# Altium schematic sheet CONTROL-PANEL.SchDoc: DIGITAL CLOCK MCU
size A4; Author: Én; Organization: PIF Club; Address1: Room 304, B1 Block; Address2: HCMUT; Address3: 268 Ly Thuong Kiet St.; Address4: Ward 14, District 10, HCMC; Revision: v1.0; SheetNumber: 2; SheetTotal: 2; ProjectTitle: DIGITAL CLOCK MCU
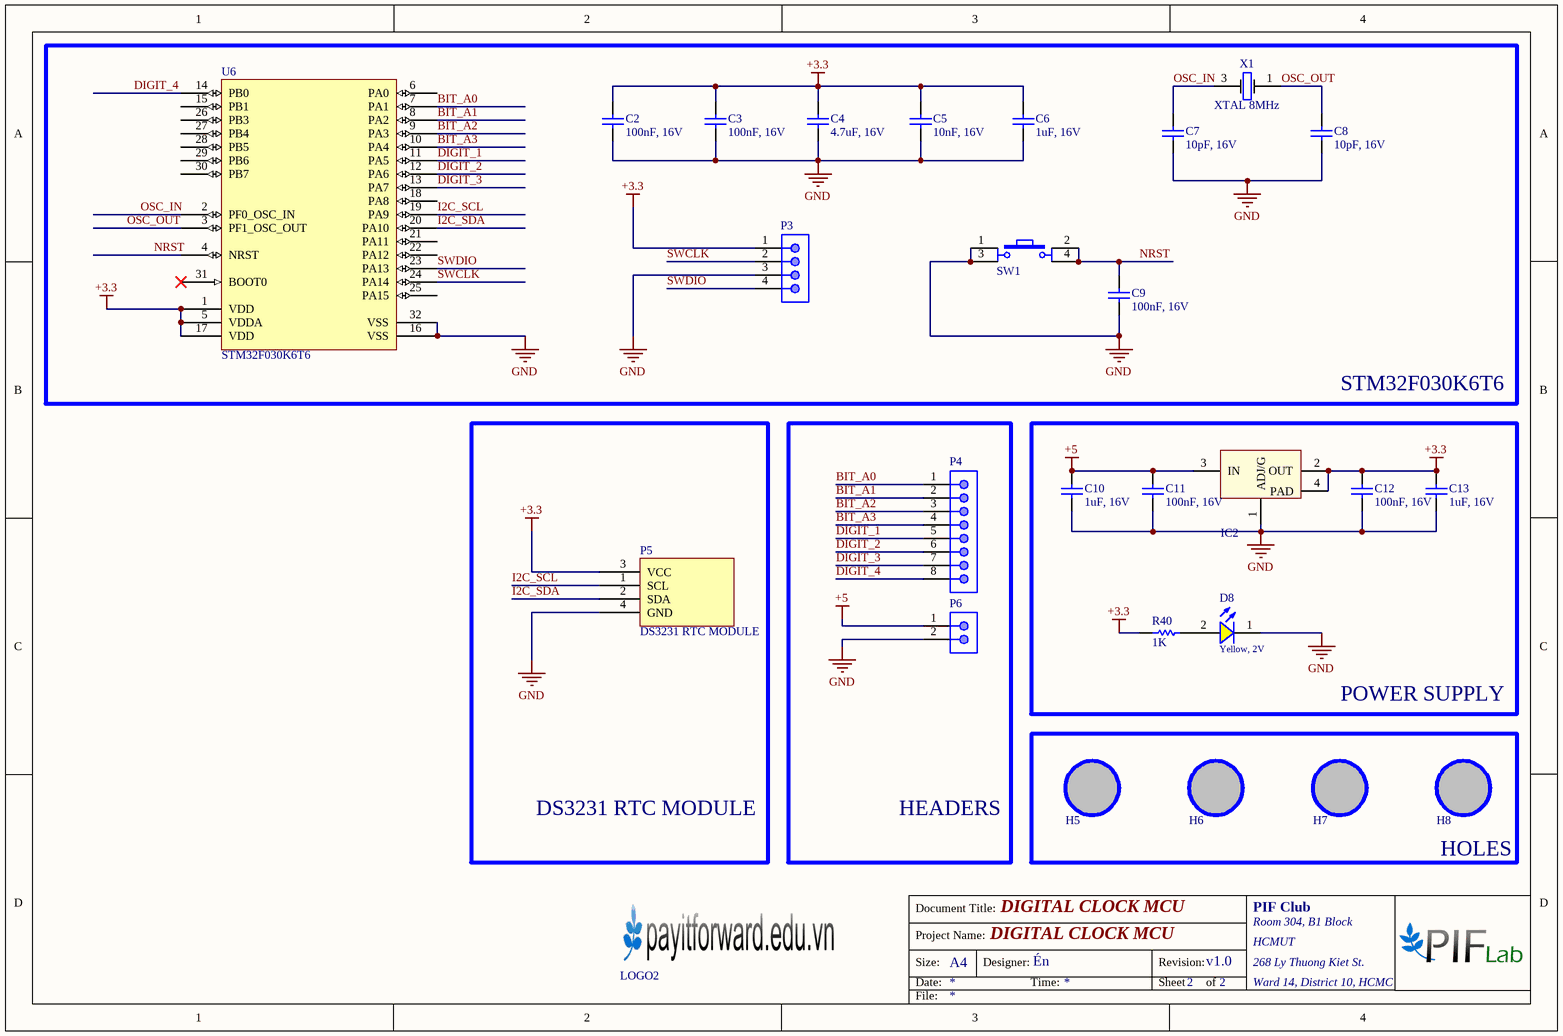
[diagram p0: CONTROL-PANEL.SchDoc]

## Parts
C2  value 100nF, 16V  [CAP-SM-0603]  (hidden comment: Cap Non-Pol SMD)
C3  value 100nF, 16V  [CAP-SM-0603]  (hidden comment: Cap Non-Pol SMD)
C4  value 4.7uF, 16V  [CAP-SM-0603]  (hidden comment: Cap Non-Pol SMD)
C5  value 10nF, 16V  [CAP-SM-0603]  (hidden comment: Cap Non-Pol SMD)
C6  value 1uF, 16V  [CAP-SM-0603]  (hidden comment: Cap Non-Pol SMD)
C7  value 10pF, 16V  [CAP-SM-0603]  (hidden comment: Cap Non-Pol SMD)
C8  value 10pF, 16V  [CAP-SM-0603]  (hidden comment: Cap Non-Pol SMD)
C9  value 100nF, 16V  [CAP-SM-0603]  (hidden comment: Cap Non-Pol SMD)
C10  value 1uF, 16V  [CAP-SM-0603]  (hidden comment: Cap Non-Pol SMD)
C11  value 100nF, 16V  [CAP-SM-0603]  (hidden comment: Cap Non-Pol SMD)
C12  value 100nF, 16V  [CAP-SM-0603]  (hidden comment: Cap Non-Pol SMD)
C13  value 1uF, 16V  [CAP-SM-0603]  (hidden comment: Cap Non-Pol SMD)
D8  Yellow, 2V  [WL-SMCW_0603_H=0.7mm]
H5  Hole  [LO KHOAN 3MM]  (value not drawn)
H6  Hole  [LO KHOAN 3MM]  (value not drawn)
H7  Hole  [LO KHOAN 3MM]  (value not drawn)
H8  Hole  [LO KHOAN 3MM]  (value not drawn)
IC2  LM1117  [SOT223-4N]  (value not drawn)
LOGO2  LOGO PIF  [PIF LOGO SMALL TOP]  (value not drawn)
P3  61900411121  [61900411121]  (value not drawn)
P4  62000811622  [62000811622]  (value not drawn)
P5  DS3231 RTC MODULE  [DS3231 RTC MODULE]
P6  62000211622  [62000211622]  (value not drawn)
R40  value 1K  [RES-SM-0603]  (hidden comment: RESISTOR SMD)
SW1  SW  [Tact SW 4 pin]  (value not drawn)
U6  STM32F030K6T6  [STM32F030K6T6]
X1  XTAL 8MHz  [XTAL 3225]

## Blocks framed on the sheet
STM32F030K6T6: C2-C9 P3 SW1 U6 X1
DS3231 RTC MODULE: P5
HEADERS: P4 P6
POWER SUPPLY: C10-C13 D8 IC2 R40
HOLES: H5-H8

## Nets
+3.3: C2.2 C3.2 C4.2 C5.2 C6.2 C12.2 C13.2 IC2.2(OUT) IC2.4(PAD) P3.1 P5.3(VCC) R40.2 U6.1(VDD) U6.5(VDDA) U6.17(VDD)
+5: C10.2 C11.2 IC2.3(IN) P6.1
GND: C2.1 C3.1 C4.1 C5.1 C6.1 C7.1 C8.1 C9.1 C10.1 C11.1 C12.1 C13.1 D8.1(K) IC2.1(ADJ/G) P3.3 P5.4(GND) P6.2 SW1.1 SW1.3 U6.16(VSS) U6.32(VSS)
BIT_A0: P4.1 U6.7(PA1)
BIT_A1: P4.2 U6.8(PA2)
BIT_A2: P4.3 U6.9(PA3)
BIT_A3: P4.4 U6.10(PA4)
DIGIT_1: P4.5 U6.11(PA5)
DIGIT_2: P4.6 U6.12(PA6)
DIGIT_3: P4.7 U6.13(PA7)
DIGIT_4: P4.8 U6.14(PB0)
I2C_SCL: P5.1(SCL) U6.19(PA9)
I2C_SDA: P5.2(SDA) U6.20(PA10)
NRST: C9.2 SW1.2 SW1.4 U6.4(NRST)
OSC_IN: C7.2 U6.2(PF0_OSC_IN) X1.3
OSC_OUT: C8.2 U6.3(PF1_OSC_OUT) X1.1
SWCLK: P3.2 U6.24(PA14)
SWDIO: P3.4 U6.23(PA13)
NetD8_2: D8.2(A) R40.1

Not connected (* = marked no-connect by the designer): H5 1; H6 1; H7 1; H8 1; U6 6(PA0) 15(PB1) 18(PA8) 21(PA11) 22(PA12) 25(PA15) 26(PB3) 27(PB4) 28(PB5) 29(PB6) 30(PB7) 31(BOOT0)*

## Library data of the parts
C2-C13 = Cap Non-Pol SMD: Capacitor
D8 = 150060YS75000: WL-SMCW SMT Mono-color Chip LED Waterclear, size 0603, Yellow, 2V, 140deg; Chip Technology: AlInGaP; Dominant Wavelength typ.: 590nm; Luminous Intensity typ.: 120mcd; Peak Wavelength typ.: 595nm
H5-H8 = Hole: Hole 3mm
IC2 = LM1117: Available in 1.8V, 2.5V, 2.85V, 3.3V, 5V, and  Adjustable Versions; Value: LM317
P3 = 61900411121: WR-WTB THT Male Vertical Locking Header, pitch 2.54mm, 4p; Pin Number: 4; Contact Resistance: 20mOhm; Rated Current: 3A; Withstanding Voltage: 1000VAC; Working Voltage: 250VAC
P4 = 62000811622: WR-WTB Male Vertical Shrouded Header, pitch 2mm, 8p; Pin Number: 8; Contact Resistance: 20mOhm; Rated Current: 2A; Withstanding Voltage: 800VAC; Working Voltage: 125VAC
P6 = 62000211622: WR-WTB Male Vertical Shrouded Header, pitch 2mm, 2p; Pin Number: 2; Contact Resistance: 20mOhm; Rated Current: 2A; Withstanding Voltage: 800VAC; Working Voltage: 125VAC
R40 = RESISTOR SMD: Resistor
SW1 = Tact SW - 4Pin: Switch button 4 pin; Value: Button chip 4 pin
U6 = STM32F030K6T6: ARM Cortex M0 Microcontroller IC 32-Bit 48MHz 32KB FLASH, 32-LQFP; Mfr: STMicroelectronics; Number of I/O: 26; Program Memory Size: 32KB (32K x 8); Connectivity: I²C, SPI, UART/USART; Peripherals: DMA, POR, PWM, WDT
X1 = XTAL: Value: 16MHz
